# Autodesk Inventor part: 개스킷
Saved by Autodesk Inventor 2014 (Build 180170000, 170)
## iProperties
Created: 2026-10
Part Number: 개스킷
Material: 일반
Document SubType Name: Modeling
Designer: dg
Density: 1 g/cm^3
Appearance: 기본값
Author: dg
Author: jhkim
Creation Date: 2026-09-29
Sending System: Autodesk Inventor 2027
Preprocessor: ST-DEVELOPER v20.1
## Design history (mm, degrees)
node "개스킷1"
node "솔리드1"
node "기준1"
